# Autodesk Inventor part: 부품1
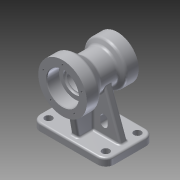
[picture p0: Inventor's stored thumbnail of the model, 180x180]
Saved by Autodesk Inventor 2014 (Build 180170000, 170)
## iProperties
Created: 2015-08
Part Number: 부품1
Material: 알루미늄 6061
Document SubType Name: Modeling
Designer: SCD-A08
Density: 2.71 g/cm^3
Appearance: 알루미늄 - 평지
Mass: 1077.91 g
Surface Area: 731.532 cm^2
Volume: 397.754 cm^3
Author: SCD-A08
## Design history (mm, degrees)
sketch "스케치6"
  geometry: L1 (-61, 40)-(61, 40); L2 (61, 40)-(61, -40); L3 (61, -40)-(-61, -40); L4 (-61, -40)-(-61, 40); 3 further points
  constraints: 8 end point, 2 midpoint, 2 parallel, 1 horizontal, 1 horizontal alignment, 1 perpendicular, 1 vertical alignment
  dimensions: "d32" = 122 distance of L1.start L1.end; "d33" = 80 distance of L1.end L2.end
extrude "돌출6" new body sketch "스케치6" distance "d34" = 12; taper "d35" = 0 deg
node "작업 평면3"
sketch "스케치7"
  geometry: L1 (0, 40)-(0, -50); L2 (0, 40)-(-35, 40); L3 (-35, 40)-(-35, 20); L4 (-35, 20)-(-26, 14.804); L5 (-26, 14.804)-(-26, -13.315); L6 (-26, -13.315)-(-40, -30); L7 (-40, -30)-(-40, -50); L8 (-40, -50)-(0, -50); L9 (-61, 40)-(61, 40) reference; 3 further points
  constraints: 16 end point, 3 perpendicular, 2 coincident, 2 midpoint, 2 parallel, 1 vertical
  dimensions: "d37" = 90 distance of L1.start L1.end; "d38" = 20 distance of L2.end L3.end; "d39" = 20 distance of L6.end L7.end; "d40" = 70 diameter of L3 L1; "d41" = 80 diameter of L7 L1; "d42" = 52 diameter of L5 L1; "d43" = 60 deg angle of L5 L4; "d44" = 40 deg angle of L6 L5
revolve "회전2" sketch "스케치7" stored, may be unused: angle "d45" = 90 deg
sketch "스케치8"
  geometry: L1 (-61, 12)-(61, 12) reference; L2 (-25.091, 83.185)-(-51, 12); L3 (0, 90)-(0, 0); L4 (25.091, 83.185)-(51, 12); L5 (51, 12)-(-51, 12); A1 r 26 centre (0, 90) between (-25.091, 83.185) and (25.091, 83.185)
  constraints: 8 end point, 2 point on circle, 2 symmetric about line, 1 centre point, 1 coincident, 1 collinear, 1 perpendicular, 1 point on line, 2 other
  dimensions: "d46" = 10 distance of L1.start L2.end; "d47" = 70 deg angle of L1 L2
extrude "돌출7" join sketch "스케치8" stored distance "d48" = 12; taper "d49" = 0 deg
sketch "스케치9"
  geometry: L1 (-40, 12)-(40, 12) reference; L2 (30, 12)-(30, 90); L3 (30, 90)-(-43.754, 90); L4 (-43.754, 90)-(-30, 12); L5 (30, 12)-(-30, 12); 1 further point
  constraints: 8 end point, 2 perpendicular, 2 point on line, 1 collinear
  dimensions: "d50" = 10 distance of L2.start L1.end; "d51" = 10 distance of L1.start L4.end; "d52" = 80 deg angle of L1 L4; "d53" = 78 distance of L2.start L2.end
extrude "돌출8" join sketch "스케치9" stored distance "d54" = 12; taper "d55" = 0 deg
sketch "스케치10"
  geometry: L1 (-50, 50)-(-50, 130) reference; L2 (-50, 90)-(40, 90); L3 (-50, 116)-(-30, 116); L4 (-30, 116)-(-30, 109); L5 (-30, 109)-(-30, 109); L6 (-27, 106)-(-27, 106); L7 (-27, 106)-(23, 106); L8 (23, 106)-(23, 110); L9 (40, 55)-(40, 125) reference; L10 (23, 110)-(40, 110); L11 (-50, 116)-(-50, 90); L12 (40, 110)-(40, 90); A1 r 3 centre (-30, 106) between (-27, 106) and (-30, 109); 2 further points
  constraints: 20 end point, 5 parallel, 4 point on line, 3 perpendicular, 2 midpoint, 2 point on circle, 2 tangent, 1 centre point, 1 collinear
  dimensions: "d56" = 52 diameter of L3 L2; "d57" = 20 distance of L3.start L3.end; "d58" = 38 diameter of L5 L2; "d59" = 3 distance of L4.end point (-27, 109); "d60" = 32 diameter of L7 L2; "d61" = 17 distance of L8.end L10.end; "d62" = 40 diameter of L10 L2; "d63" = 3 radius of A1
revolve "회전3" sketch "스케치10" stored, may be unused: angle "d64" = 90 deg
chamfer "모따기1" distance "d65" = 1; stored, may be unused: second distance "d66" = 2, angle "d67" = 45 deg
fillet "모깎기1" dims "d68" = 0.3
fillet "모깎기2" dims "d69" = 14
sketch "스케치11"
  geometry: A1 r 14 centre (-47, 26) between (-47, 40) and (-61, 26) reference; 2 further points
  constraints: 1 coincident
hole "구멍1" sketch "스케치11" at (-47, 26) diameter "d70" = 12; stored, may be unused: countersink angle "d74" = 90 deg, drill point angle "d76" = 118 deg; dims "d71" = 6, "d72" = 4, "d73" = 2, "d75" = 8
sketch "스케치12"
  geometry: C1 r 35 at (0, 0) reference; 2 further points
  constraints: 1 vertical alignment
  dimensions: "d85" = 27 distance of C1.centre point (0, -27)
hole "구멍2" sketch "스케치12" at (0, -27) diameter "d86" = 3.242; stored, may be unused: countersink angle "d90" = 90 deg, drill point angle "d92" = 118 deg; dims "d87" = 10, "d88" = 4, "d89" = 2, "d91" = 13
sketch "스케치13"
  geometry: C1 r 40 at (0, 0) reference; 3 further points
  constraints: 1 coincident, 1 vertical alignment
  dimensions: "d96" = 33 distance of point (0, 33) C1.centre
hole "구멍3" sketch "스케치13" at (0, 33) diameter "d97" = 3.242; stored, may be unused: countersink angle "d101" = 90 deg, drill point angle "d103" = 118 deg; dims "d98" = 10, "d99" = 4, "d100" = 2, "d102" = 13
sketch "스케치14"
  geometry: L1 (12, -26)-(12, 26) reference; L2 (52.119, 30)-(15, 30) reference; 2 further points
  constraints: 1 other
feature "엠보싱1" sketch "스케치14" dims "d32" = 122, "d33" = 80, "d109" = 0.5, "d110" = 0
sketch "스케치15"
  geometry: L1 (24, 37)-(24, 30); L2 (18, 37)-(18, 30); L3 (30, 30)-(30, 37); L4 (-6, 12)-(-6, 64.702) reference; L5 (-6, 12)-(-51, 12) reference; A1 r 6 centre (24, 37) between (30, 37) and (18, 37); A2 r 6 centre (24, 30) between (18, 30) and (30, 30); 2 further points
  constraints: 8 end point, 4 point on circle, 4 tangent, 2 centre point, 2 parallel, 1 midpoint
  dimensions: "d112" = 12 distance between parallel lines of L3 L2; "d113" = 7 distance of L1.end L1.start; "d114" = 24 horizontal distance of point (24, 33.5) point (0, 0); "d121" = 18 distance from line of L1.end L5
extrude "돌출9" cut sketch "스케치15" stored distance "d116" = 10; taper "d117" = 0 deg
fillet "모깎기5" dims "d118" = 3
fillet "모깎기6" dims "d119" = 5
fillet "모깎기7" dims "d120" = 3
node "솔리드2"
pattern_linear "직사각형 패턴1" dims "d79" = 94, "d82" = 52
pattern_circular "원형 패턴1" dims angle "d94" = 360 deg
pattern_circular "원형 패턴2" dims angle "d105" = 360 deg
mirror "대칭2"
